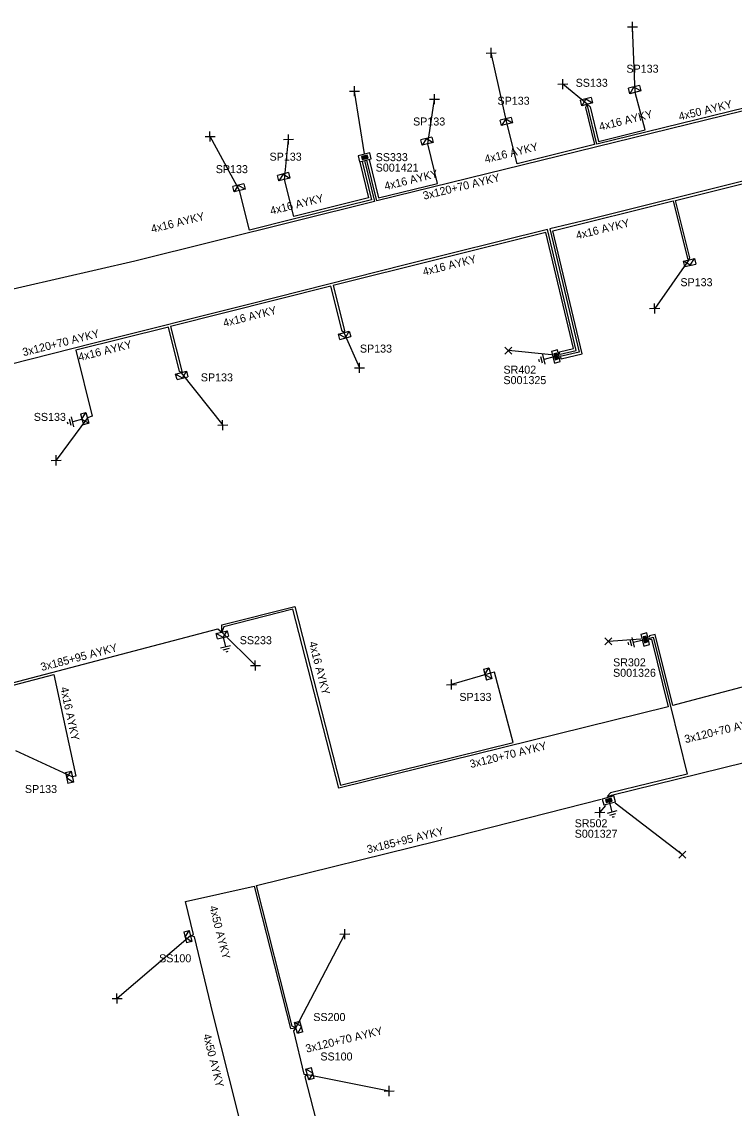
# Model space of a CAD drawing. Extents: x -762500 to -761285, y -1155006 to -1154135.
# Drawn here: x -762296.3 to -762207.7, y -1154708.4 to -1154573.4 of the extents above; entities that cross this region are included whole.
import ezdxf

# ---------------------------------------------------------------- set-up
doc = ezdxf.new("R2010")
doc.units = 0
for name, color, linetype in [('Vrstva 15', 7, 'Continuous'), ('Vrstva 28', 7, 'Continuous'), ('Vrstva 29', 7, 'Continuous'), ('Vrstva 30', 7, 'Continuous'), ('Vrstva 31', 7, 'Continuous'), ('Vrstva 33', 7, 'Continuous'), ('Vrstva 34', 7, 'Continuous'), ('Vrstva 5', 7, 'Continuous'), ('Vrstva 59', 7, 'Continuous'), ('Vrstva 6', 7, 'Continuous')]:
    doc.layers.add(name, color=color, linetype=linetype)

msp = doc.modelspace()

# ---------------------------------------------------------------- linework, layer by layer
at = {"layer": 'Vrstva 15'}
for points in [[(-762231.581, -1154615.789), (-762231.771, -1154615.024)], [(-762231.221, -1154615.948), (-762231.524, -1154614.735)], [(-762230.16, -1154615.039), (-762231.373, -1154615.341)], [(-762231.979, -1154615.492), (-762232.01, -1154615.368)], [(-762231.947, -1154615.621), (-762231.979, -1154615.492)], [(-762290.558, -1154623.256), (-762290.592, -1154623.132)], [(-762290.524, -1154623.384), (-762290.558, -1154623.256)], [(-762290.155, -1154623.545), (-762290.359, -1154622.784)], [(-762289.793, -1154623.697), (-762290.116, -1154622.49)], [(-762288.747, -1154622.77), (-762289.955, -1154623.094)], [(-762271.271, -1154649.85), (-762270.969, -1154651.063)], [(-762220.481, -1154650.959), (-762220.671, -1154650.195)], [(-762220.121, -1154651.118), (-762220.424, -1154649.905)], [(-762219.06, -1154650.209), (-762220.273, -1154650.511)], [(-762270.362, -1154650.912), (-762271.575, -1154651.214)], [(-762270.521, -1154651.271), (-762271.285, -1154651.462)], [(-762270.818, -1154651.67), (-762270.942, -1154651.701)], [(-762270.689, -1154651.637), (-762270.818, -1154651.67)], [(-762220.879, -1154650.662), (-762220.91, -1154650.538)], [(-762220.847, -1154650.791), (-762220.879, -1154650.662)], [(-762223.26, -1154670.397), (-762222.936, -1154671.604)], [(-762222.333, -1154671.442), (-762223.54, -1154671.766)], [(-762222.485, -1154671.804), (-762223.246, -1154672.008)], [(-762222.775, -1154672.208), (-762222.898, -1154672.241)], [(-762222.646, -1154672.174), (-762222.775, -1154672.208)]]:
    msp.add_lwpolyline(points, dxfattribs=at)
at = {"layer": 'Vrstva 28'}
for points in [[(-762253.025, -1154589.675), (-762254.48, -1154590.038)], [(-762254.48, -1154590.038), (-762254.299, -1154590.765)], [(-762254.299, -1154590.765), (-762252.844, -1154590.402)], [(-762253.34, -1154589.948), (-762254.062, -1154590.128)], [(-762254.062, -1154590.128), (-762253.971, -1154590.495)], [(-762253.375, -1154590.005), (-762254.005, -1154590.162)], [(-762254.005, -1154590.162), (-762253.936, -1154590.437)], [(-762253.971, -1154590.495), (-762253.249, -1154590.315)], [(-762253.409, -1154590.063), (-762253.948, -1154590.197)], [(-762253.948, -1154590.197), (-762253.902, -1154590.38)], [(-762253.936, -1154590.437), (-762253.306, -1154590.28)], [(-762253.902, -1154590.38), (-762253.363, -1154590.246)], [(-762253.444, -1154590.12), (-762253.891, -1154590.231)], [(-762253.891, -1154590.231), (-762253.868, -1154590.323)], [(-762253.868, -1154590.323), (-762253.421, -1154590.211)], [(-762253.472, -1154590.176), (-762253.839, -1154590.267)], [(-762253.421, -1154590.211), (-762253.444, -1154590.12)], [(-762253.363, -1154590.246), (-762253.409, -1154590.063)], [(-762253.306, -1154590.28), (-762253.375, -1154590.005)], [(-762253.249, -1154590.315), (-762253.34, -1154589.948)], [(-762252.844, -1154590.402), (-762253.025, -1154589.675)], [(-762229.717, -1154614.153), (-762230.445, -1154614.335)], [(-762230.445, -1154614.335), (-762230.082, -1154615.79)], [(-762229.805, -1154614.558), (-762230.172, -1154614.65)], [(-762230.172, -1154614.65), (-762229.992, -1154615.372)], [(-762229.839, -1154614.616), (-762230.114, -1154614.684)], [(-762230.114, -1154614.684), (-762229.957, -1154615.315)], [(-762229.874, -1154614.673), (-762230.057, -1154614.719)], [(-762230.057, -1154614.719), (-762229.923, -1154615.257)], [(-762229.908, -1154614.73), (-762230, -1154614.753)], [(-762230, -1154614.753), (-762229.888, -1154615.2)], [(-762229.944, -1154614.782), (-762229.853, -1154615.149)], [(-762229.923, -1154615.257), (-762229.739, -1154615.212)], [(-762229.797, -1154615.177), (-762229.908, -1154614.73)], [(-762229.888, -1154615.2), (-762229.797, -1154615.177)], [(-762229.739, -1154615.212), (-762229.874, -1154614.673)], [(-762229.682, -1154615.246), (-762229.839, -1154614.616)], [(-762229.625, -1154615.28), (-762229.805, -1154614.558)], [(-762229.354, -1154615.609), (-762229.717, -1154614.153)], [(-762230.082, -1154615.79), (-762229.354, -1154615.609)], [(-762229.992, -1154615.372), (-762229.625, -1154615.28)], [(-762229.957, -1154615.315), (-762229.682, -1154615.246)], [(-762218.618, -1154649.323), (-762219.346, -1154649.505)], [(-762219.346, -1154649.505), (-762218.983, -1154650.96)], [(-762218.705, -1154649.729), (-762219.072, -1154649.82)], [(-762219.072, -1154649.82), (-762218.892, -1154650.542)], [(-762218.74, -1154649.786), (-762219.015, -1154649.854)], [(-762219.015, -1154649.854), (-762218.858, -1154650.485)], [(-762218.774, -1154649.843), (-762218.958, -1154649.889)], [(-762218.958, -1154649.889), (-762218.823, -1154650.428)], [(-762218.809, -1154649.9), (-762218.9, -1154649.923)], [(-762218.9, -1154649.923), (-762218.789, -1154650.37)], [(-762218.845, -1154649.952), (-762218.753, -1154650.319)], [(-762218.697, -1154650.347), (-762218.809, -1154649.9)], [(-762218.64, -1154650.382), (-762218.774, -1154649.843)], [(-762218.583, -1154650.416), (-762218.74, -1154649.786)], [(-762218.525, -1154650.451), (-762218.705, -1154649.729)], [(-762218.255, -1154650.779), (-762218.618, -1154649.323)], [(-762218.983, -1154650.96), (-762218.255, -1154650.779)], [(-762218.892, -1154650.542), (-762218.525, -1154650.451)], [(-762218.858, -1154650.485), (-762218.583, -1154650.416)], [(-762218.823, -1154650.428), (-762218.64, -1154650.382)], [(-762218.789, -1154650.37), (-762218.697, -1154650.347)], [(-762222.705, -1154669.582), (-762224.154, -1154669.97)], [(-762224.154, -1154669.97), (-762223.96, -1154670.694)], [(-762223.96, -1154670.694), (-762222.511, -1154670.306)], [(-762223.028, -1154669.858), (-762223.747, -1154670.05)], [(-762223.747, -1154670.05), (-762223.649, -1154670.415)], [(-762223.062, -1154669.916), (-762223.689, -1154670.084)], [(-762223.689, -1154670.084), (-762223.616, -1154670.358)], [(-762223.649, -1154670.415), (-762222.93, -1154670.223)], [(-762223.095, -1154669.973), (-762223.631, -1154670.117)], [(-762223.631, -1154670.117), (-762223.582, -1154670.3)], [(-762223.616, -1154670.358), (-762222.988, -1154670.189)], [(-762223.582, -1154670.3), (-762223.046, -1154670.156)], [(-762223.128, -1154670.031), (-762223.573, -1154670.151)], [(-762223.573, -1154670.151), (-762223.549, -1154670.242)], [(-762223.549, -1154670.242), (-762223.104, -1154670.123)], [(-762223.521, -1154670.185), (-762223.156, -1154670.088)], [(-762223.104, -1154670.123), (-762223.128, -1154670.031)], [(-762223.046, -1154670.156), (-762223.095, -1154669.973)], [(-762222.988, -1154670.189), (-762223.062, -1154669.916)], [(-762222.93, -1154670.223), (-762223.028, -1154669.858)], [(-762222.511, -1154670.306), (-762222.705, -1154669.582)]]:
    msp.add_lwpolyline(points, dxfattribs=at)
at = {"layer": 'Vrstva 31'}
for points in [[(-762219.528, -1154581.301), (-762220.886, -1154581.639)], [(-762219.528, -1154581.301), (-762219.358, -1154581.98), (-762220.717, -1154582.319), (-762220.886, -1154581.639)], [(-762220.207, -1154581.47), (-762220.717, -1154582.319)], [(-762220.207, -1154581.47), (-762219.358, -1154581.98)], [(-762225.508, -1154582.791), (-762226.866, -1154583.129)], [(-762225.508, -1154582.791), (-762225.338, -1154583.47), (-762226.697, -1154583.809), (-762226.866, -1154583.129)], [(-762226.187, -1154582.96), (-762226.697, -1154583.809)], [(-762226.187, -1154582.96), (-762225.338, -1154583.47)], [(-762235.458, -1154585.261), (-762236.816, -1154585.599)], [(-762235.458, -1154585.261), (-762235.288, -1154585.94), (-762236.647, -1154586.279), (-762236.816, -1154585.599)], [(-762236.137, -1154585.43), (-762236.647, -1154586.279)], [(-762236.137, -1154585.43), (-762235.288, -1154585.94)], [(-762245.318, -1154587.7), (-762246.676, -1154588.039)], [(-762245.318, -1154587.7), (-762245.148, -1154588.38), (-762246.507, -1154588.718), (-762246.676, -1154588.039)], [(-762245.997, -1154587.87), (-762246.507, -1154588.718)], [(-762245.997, -1154587.87), (-762245.148, -1154588.38)], [(-762263.137, -1154592.131), (-762264.496, -1154592.47)], [(-762263.137, -1154592.131), (-762262.968, -1154592.81), (-762264.326, -1154593.149), (-762264.496, -1154592.47)], [(-762268.698, -1154593.51), (-762270.056, -1154593.849)], [(-762268.698, -1154593.51), (-762268.528, -1154594.189), (-762269.887, -1154594.528), (-762270.056, -1154593.849)], [(-762263.817, -1154592.3), (-762264.326, -1154593.149)], [(-762263.817, -1154592.3), (-762262.968, -1154592.81)], [(-762269.377, -1154593.68), (-762269.887, -1154594.528)], [(-762269.377, -1154593.68), (-762268.528, -1154594.189)], [(-762213.897, -1154603.801), (-762214.055, -1154603.118), (-762212.69, -1154602.804), (-762212.533, -1154603.486)], [(-762213.215, -1154603.643), (-762212.69, -1154602.804)], [(-762213.215, -1154603.643), (-762214.055, -1154603.118)], [(-762213.897, -1154603.801), (-762212.533, -1154603.486)], [(-762256.748, -1154612.859), (-762256.929, -1154612.182), (-762255.576, -1154611.82), (-762255.395, -1154612.496)], [(-762256.071, -1154612.677), (-762256.929, -1154612.182)], [(-762256.748, -1154612.859), (-762255.395, -1154612.496)], [(-762256.071, -1154612.677), (-762255.576, -1154611.82)], [(-762276.978, -1154617.848), (-762277.159, -1154617.172), (-762275.807, -1154616.81), (-762275.626, -1154617.486)], [(-762276.302, -1154617.667), (-762277.159, -1154617.172)], [(-762276.978, -1154617.848), (-762275.626, -1154617.486)], [(-762276.302, -1154617.667), (-762275.807, -1154616.81)], [(-762288.989, -1154622.102), (-762288.313, -1154621.921), (-762287.95, -1154623.273), (-762288.626, -1154623.454)], [(-762288.808, -1154622.778), (-762288.313, -1154621.921)], [(-762288.989, -1154622.102), (-762288.626, -1154623.454)], [(-762288.808, -1154622.778), (-762287.95, -1154623.273)], [(-762271.942, -1154650.079), (-762272.112, -1154649.4), (-762270.753, -1154649.061), (-762270.584, -1154649.74)], [(-762271.263, -1154649.91), (-762272.112, -1154649.4)], [(-762271.942, -1154650.079), (-762270.584, -1154649.74)], [(-762271.263, -1154649.91), (-762270.753, -1154649.061)], [(-762238.909, -1154653.832), (-762238.232, -1154653.651), (-762237.87, -1154655.003), (-762238.546, -1154655.184)], [(-762238.909, -1154653.832), (-762238.546, -1154655.184)], [(-762238.727, -1154654.508), (-762238.232, -1154653.651)], [(-762238.727, -1154654.508), (-762237.87, -1154655.003)], [(-762290.831, -1154666.658), (-762290.147, -1154666.513), (-762289.855, -1154667.882), (-762290.54, -1154668.028)], [(-762290.686, -1154667.343), (-762290.147, -1154666.513)], [(-762290.831, -1154666.658), (-762290.54, -1154668.028)], [(-762290.686, -1154667.343), (-762289.855, -1154667.882)], [(-762276.159, -1154686.478), (-762275.48, -1154686.308), (-762275.141, -1154687.667), (-762275.821, -1154687.836)], [(-762276.159, -1154686.478), (-762275.821, -1154687.836)], [(-762275.99, -1154687.157), (-762275.48, -1154686.308)], [(-762275.99, -1154687.157), (-762275.141, -1154687.667)], [(-762261.351, -1154698.918), (-762262.028, -1154699.099), (-762262.39, -1154697.747), (-762261.714, -1154697.566)], [(-762261.351, -1154698.918), (-762261.714, -1154697.566)], [(-762261.533, -1154698.242), (-762262.39, -1154697.747)], [(-762261.533, -1154698.242), (-762262.028, -1154699.099)], [(-762259.932, -1154704.698), (-762260.608, -1154704.879), (-762260.97, -1154703.527), (-762260.294, -1154703.346)], [(-762260.113, -1154704.022), (-762260.97, -1154703.527)], [(-762260.113, -1154704.022), (-762260.608, -1154704.879)], [(-762259.932, -1154704.698), (-762260.294, -1154703.346)]]:
    msp.add_lwpolyline(points, dxfattribs=at)
at = {"layer": 'Vrstva 34'}
for points in [[(-762220.369, -1154574.625), (-762220.391, -1154573.375)], [(-762221.005, -1154574.011), (-762219.755, -1154573.989)], [(-762238.565, -1154577.261), (-762237.315, -1154577.239)], [(-762237.929, -1154577.875), (-762237.951, -1154576.625)], [(-762254.929, -1154582.625), (-762254.951, -1154581.375)], [(-762229.675, -1154581.131), (-762228.425, -1154581.109)], [(-762229.039, -1154581.745), (-762229.061, -1154580.495)], [(-762255.565, -1154582.011), (-762254.315, -1154581.989)], [(-762244.989, -1154583.625), (-762245.011, -1154582.375)], [(-762245.625, -1154583.011), (-762244.375, -1154582.989)], [(-762273.505, -1154587.641), (-762272.255, -1154587.619)], [(-762272.869, -1154588.255), (-762272.891, -1154587.005)], [(-762263.755, -1154588.011), (-762262.505, -1154587.989)], [(-762263.119, -1154588.625), (-762263.141, -1154587.375)], [(-762217.619, -1154609.625), (-762217.641, -1154608.375)], [(-762218.255, -1154609.011), (-762217.005, -1154608.989)], [(-762236.252, -1154613.808), (-762235.368, -1154614.692)], [(-762236.252, -1154614.692), (-762235.368, -1154613.808)], [(-762254.935, -1154616.391), (-762253.685, -1154616.369)], [(-762254.299, -1154617.005), (-762254.321, -1154615.755)], [(-762271.299, -1154624.125), (-762271.321, -1154622.875)], [(-762271.935, -1154623.511), (-762270.685, -1154623.489)], [(-762291.989, -1154628.505), (-762292.011, -1154627.255)], [(-762292.625, -1154627.891), (-762291.375, -1154627.869)], [(-762223.822, -1154649.938), (-762222.938, -1154650.822)], [(-762223.822, -1154650.822), (-762222.938, -1154649.938)], [(-762267.239, -1154654.005), (-762267.261, -1154652.755)], [(-762267.875, -1154653.391), (-762266.625, -1154653.369)], [(-762243.505, -1154655.761), (-762242.255, -1154655.739)], [(-762242.869, -1154656.375), (-762242.891, -1154655.125)], [(-762225.075, -1154671.631), (-762223.825, -1154671.609)], [(-762224.439, -1154672.245), (-762224.461, -1154670.995)], [(-762214.632, -1154676.438), (-762213.748, -1154677.322)], [(-762214.632, -1154677.322), (-762213.748, -1154676.438)], [(-762256.755, -1154686.761), (-762255.505, -1154686.739)], [(-762256.119, -1154687.375), (-762256.141, -1154686.125)], [(-762285.065, -1154694.761), (-762283.815, -1154694.739)], [(-762284.429, -1154695.375), (-762284.451, -1154694.125)], [(-762250.619, -1154706.875), (-762250.641, -1154705.625)], [(-762251.255, -1154706.261), (-762250.005, -1154706.239)]]:
    msp.add_lwpolyline(points, dxfattribs=at)
at = {"layer": 'Vrstva 5'}
for points in [[(-762144.24, -1154589.69), (-762144.5, -1154589.93), (-762146.6, -1154590.48), (-762149.55, -1154579.17), (-762169.85, -1154584.09), (-762188.5, -1154588.71), (-762206.51, -1154593.14), (-762225.77, -1154597.95), (-762230.65, -1154599.12), (-762227.01, -1154614.44), (-762229.36, -1154614.99), (-762229.4, -1154614.91)], [(-762197.61, -1154581.45), (-762197.64, -1154582.25), (-762252.17, -1154595.62), (-762253.42, -1154590.57)], [(-762197.74, -1154581.48), (-762197.92, -1154582.01), (-762224.8, -1154588.59), (-762226.02, -1154583.64)], [(-762226.02, -1154583.64), (-762225.65, -1154583.94), (-762224.6, -1154588.25), (-762218.83, -1154586.82), (-762220.04, -1154582.15)], [(-762226.02, -1154583.64), (-762226.23, -1154584.04), (-762225.09, -1154588.65), (-762234.72, -1154591.02), (-762235.97, -1154586.11)], [(-762253.13, -1154590.49), (-762251.95, -1154595.26), (-762244.62, -1154593.46), (-762245.83, -1154588.55)], [(-762253.71, -1154590.64), (-762252.46, -1154595.71), (-762282.22, -1154603.15), (-762310.37, -1154609.58), (-762326.38, -1154613.11), (-762331.12, -1154619.82), (-762328.37, -1154631.12), (-762325.93, -1154643.77), (-762326.72, -1154644.24)], [(-762254, -1154590.74), (-762252.83, -1154595.49), (-762262.57, -1154597.93), (-762267.98, -1154599.28), (-762269.21, -1154594.36)], [(-762254.29, -1154590.82), (-762253.19, -1154595.27), (-762262.49, -1154597.59), (-762263.65, -1154592.98)], [(-762229.37, -1154615.04), (-762229.27, -1154615.28), (-762226.64, -1154614.66), (-762230.29, -1154599.34), (-762215.35, -1154595.65), (-762213.56, -1154602.8), (-762213.37, -1154602.96), (-762213.27, -1154602.72), (-762215.06, -1154595.58), (-762206.44, -1154593.43), (-762191.65, -1154589.79), (-762189.42, -1154598.87), (-762190.32, -1154599.08)], [(-762229.43, -1154614.78), (-762229.39, -1154614.69), (-762227.37, -1154614.23), (-762230.95, -1154599.18), (-762248.65, -1154603.59), (-762267.92, -1154608.48), (-762287.44, -1154613.36), (-762313.42, -1154619.93), (-762315.2, -1154621.99), (-762317.02, -1154626.74), (-762315.99, -1154635.5), (-762314.32, -1154654.12), (-762314.03, -1154654.16)], [(-762229.46, -1154614.66), (-762229.46, -1154614.39), (-762227.73, -1154614), (-762231.17, -1154599.55), (-762257.58, -1154606.16), (-762256.17, -1154611.74), (-762256.25, -1154612), (-762256.45, -1154611.83), (-762257.87, -1154606.23), (-762277.78, -1154611.26), (-762276.38, -1154616.78), (-762276.48, -1154616.99), (-762276.67, -1154616.85), (-762278.06, -1154611.35), (-762289.58, -1154614.21), (-762287.54, -1154622.38), (-762288.13, -1154622.6)], [(-762179.61, -1154640.87), (-762179.07, -1154640.76), (-762178.74, -1154640.68), (-762176.71, -1154648.25), (-762194.99, -1154652.98), (-762214.28, -1154658.05), (-762215.36, -1154658.34), (-762217.56, -1154649.51), (-762218.27, -1154649.71), (-762218.34, -1154649.89)], [(-762271.43, -1154649.23), (-762271.4, -1154648.33), (-762262.36, -1154646.03), (-762256.66, -1154668.23), (-762235.23, -1154662.94), (-762237.54, -1154654.2), (-762238.05, -1154654.33)], [(-762218.28, -1154650.15), (-762218.04, -1154650.12), (-762215.94, -1154658.5), (-762256.88, -1154668.6), (-762262.58, -1154646.39), (-762271.15, -1154648.57), (-762271.43, -1154649.23)], [(-762313.99, -1154654.55), (-762314.44, -1154654.77), (-762314.15, -1154659.92), (-762271.93, -1154648.8), (-762271.43, -1154649.23)], [(-762218.31, -1154650.02), (-762217.8, -1154649.87), (-762215.65, -1154658.41), (-762213.58, -1154666.86), (-762223.11, -1154669.21), (-762223.53, -1154669.67)], [(-762223.4, -1154669.64), (-762222.98, -1154669.48), (-762140.4, -1154649.15), (-762139.3, -1154653.19)], [(-762314, -1154654.42), (-762314.75, -1154654.62), (-762314.42, -1154660.31), (-762292.28, -1154654.48), (-762289.57, -1154667.11), (-762290, -1154667.2)], [(-762262.21, -1154698.42), (-762262.67, -1154698.18), (-762267.12, -1154680.73), (-762244.6, -1154675.17), (-762224.28, -1154670)], [(-762266.94, -1154720.82), (-762266.61, -1154720.57), (-762269.53, -1154708.55), (-762272.54, -1154696.57), (-762274.83, -1154687.1), (-762275.31, -1154686.99), (-762274.92, -1154686.8), (-762275.94, -1154682.71), (-762267.41, -1154680.81), (-762262.89, -1154698.5), (-762262.21, -1154698.42)], [(-762262.21, -1154698.42), (-762262.53, -1154698.76), (-762261.22, -1154704.16), (-762260.79, -1154704.2), (-762261.11, -1154704.5), (-762254.33, -1154730.82), (-762253.96, -1154730.86), (-762254.25, -1154731.16), (-762251.07, -1154743.75), (-762248.94, -1154752.03), (-762248.56, -1154752.19), (-762248.84, -1154752.46), (-762246.69, -1154761.36), (-762246.19, -1154761.46), (-762246.59, -1154761.73), (-762240.44, -1154784.7), (-762239.02, -1154785.78), (-762237.99, -1154785.84), (-762236.53, -1154785.32), (-762235.21, -1154786.11), (-762234.52, -1154786.06)]]:
    msp.add_lwpolyline(points, dxfattribs=at)
at = {"layer": 'Vrstva 59'}
for points in [[(-762220.04, -1154582.15), (-762220.38, -1154574)], [(-762235.97, -1154586.11), (-762237.94, -1154577.25)], [(-762226.02, -1154583.64), (-762229.05, -1154581.12)], [(-762253.7, -1154589.8), (-762254.94, -1154582)], [(-762245.83, -1154588.55), (-762245, -1154583)], [(-762269.21, -1154594.36), (-762272.88, -1154587.63)], [(-762263.65, -1154592.98), (-762263.13, -1154588)], [(-762213.37, -1154602.96), (-762217.63, -1154609)], [(-762256.25, -1154612), (-762254.31, -1154616.38)], [(-762230.47, -1154614.78), (-762235.81, -1154614.25)], [(-762276.48, -1154616.99), (-762271.31, -1154623.5)], [(-762288.13, -1154622.6), (-762292, -1154627.88)], [(-762271.43, -1154649.23), (-762267.25, -1154653.38)], [(-762219.33, -1154650.11), (-762223.38, -1154650.38)], [(-762238.05, -1154654.33), (-762242.88, -1154655.75)], [(-762290, -1154667.2), (-762297, -1154664)], [(-762222.54, -1154670.46), (-762214.19, -1154676.88)], [(-762223.75, -1154670.77), (-762224.45, -1154671.62)], [(-762262.21, -1154698.42), (-762256.13, -1154686.75)], [(-762275.31, -1154686.99), (-762284.44, -1154694.75)], [(-762260.79, -1154704.2), (-762250.63, -1154706.25)]]:
    msp.add_lwpolyline(points, dxfattribs=at)

# ---------------------------------------------------------------- texts
at = {"layer": 'Vrstva 29'}
for s, p in [('S001421', (-762252.3, -1154592)), ('S001325', (-762236.42, -1154618.41)), ('S001326', (-762222.8, -1154654.78)), ('S001327', (-762227.57, -1154674.78))]:
    msp.add_text(s, height=0.9943, dxfattribs=at).set_placement(p)
at = {"layer": 'Vrstva 30'}
for s, p in [('SS333', (-762252.3, -1154590.7)), ('SR402', (-762236.42, -1154617.11)), ('SR302', (-762222.8, -1154653.48)), ('SR502', (-762227.57, -1154673.48))]:
    msp.add_text(s, height=0.9943, dxfattribs=at).set_placement(p)
at = {"layer": 'Vrstva 33'}
for s, p in [('SP133', (-762221.14, -1154579.71)), ('SS133', (-762227.45, -1154581.46)), ('SP133', (-762237.16, -1154583.69)), ('SP133', (-762247.65, -1154586.27)), ('SP133', (-762265.49, -1154590.64)), ('SP133', (-762272.17, -1154592.19)), ('SP133', (-762214.43, -1154606.24)), ('SP133', (-762254.26, -1154614.49)), ('SP133', (-762274.03, -1154618.07)), ('SS133', (-762294.79, -1154622.98)), ('SS233', (-762269.19, -1154650.73)), ('SP133', (-762241.9, -1154657.78)), ('SP133', (-762295.89, -1154669.22)), ('SS100', (-762279.21, -1154690.26)), ('SS200', (-762260.05, -1154697.56)), ('SS100', (-762259.17, -1154702.46))]:
    msp.add_text(s, height=0.9943, dxfattribs=at).set_placement(p)
at = {"layer": 'Vrstva 6'}
for s, height, rotation, p in [('4x50 AYKY', 0.9943, 13.76653, (-762214.52, -1154585.66)), ('4x16 AYKY', 0.9943, 13.95434, (-762224.41, -1154586.92)), ('4x16 AYKY', 0.9943, 13.86803, (-762238.64, -1154590.96)), ('4x16 AYKY', 0.9943, 13.78007, (-762251.09, -1154594.31)), ('3x120+70 AYKY', 0.99429, 13.77784, (-762246.29, -1154595.5)), ('4x16 AYKY', 0.9943, 13.96517, (-762265.29, -1154597.37)), ('4x16 AYKY', 0.9943, 14.01981, (-762280.09, -1154599.63)), ('4x16 AYKY', 0.9943, 13.84572, (-762227.28, -1154600.43)), ('4x16 AYKY', 0.9943, 14.06023, (-762246.31, -1154604.94)), ('4x16 AYKY', 0.9943, 14.19147, (-762271.13, -1154611.32)), ('3x120+70 AYKY', 0.99428, 14.19134, (-762296.06, -1154614.95)), ('4x16 AYKY', 0.9943, 13.97304, (-762289.12, -1154615.55)), ('3x185+95 AYKY', 0.99429, 14.75846, (-762293.79, -1154654.07)), ('4x16 AYKY', 0.9943, 284.38605, (-762260.61, -1154650.52)), ('4x16 AYKY', 0.9943, 282.08113, (-762291.49, -1154656.14)), ('3x120+70 AYKY', 0.99429, 13.78703, (-762213.79, -1154663.04)), ('3x120+70 AYKY', 0.99429, 13.85796, (-762240.48, -1154666.13)), ('3x185+95 AYKY', 0.99429, 13.8685, (-762253.26, -1154676.73)), ('4x50 AYKY', 0.9943, 284.32608, (-762272.98, -1154683.36)), ('3x120+70 AYKY', 0.99429, 13.59051, (-762260.88, -1154701.5)), ('4x50 AYKY', 0.9943, 284.10374, (-762273.76, -1154699.28))]:
    msp.add_text(s, height=height, rotation=rotation, dxfattribs=at).set_placement(p)

doc.saveas('drawing.dxf')
